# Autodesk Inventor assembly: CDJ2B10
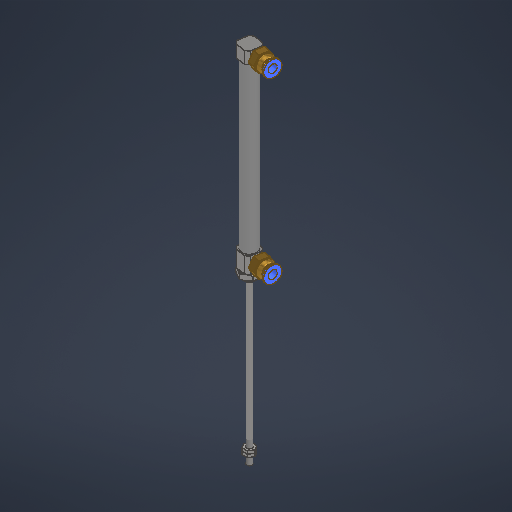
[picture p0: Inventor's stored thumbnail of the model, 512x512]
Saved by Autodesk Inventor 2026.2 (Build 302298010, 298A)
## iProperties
Created: 2026-05
Part Number: CDJ2B10
Document SubType Name: Assembly
Designer: work
Author: work
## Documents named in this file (6)
- C:\Users\work\Desktop\ARD_v1\ARD_hardware\Pneumatic fitting\CDJ2B10_100\CDJ2B10.iam
- C:\Users\work\Desktop\ARD_v1\ARD_hardware\Pneumatic fitting\CDJ2B10_100\Rod.ipt
- C:\Users\work\Desktop\ARD_v1\ARD_hardware\Pneumatic fitting\CDJ2B10_100\CDJ2B10_Body.ipt
- C:\Users\work\Desktop\ARD_v1\ARD_hardware\Pneumatic fitting\PC6-M5.ipt
- C:\Users\work\Desktop\ARD_v1\ARD_hardware\Pneumatic fitting\CDJ2B10_100\ANSI B18.2.4.5M - M8 x 1.25.ipt
- C:\Users\work\Desktop\ARD_v1\ARD_hardware\Pneumatic fitting\CDJ2B10_100\AS 1474 - M4(1).ipt
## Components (7 placed, 5 different names)
1. Rod:1 — 플러쉬:1, 플러쉬:2
2. CDJ2B10_Body:1 — 플러쉬:1
3. PC6-M5:1
4. PC6-M5:2
5. ANSI B18.2.4.5M - M8 x 1.25:1
6. AS 1474 - M4(1):1
7. AS 1474 - M4(1):2 — 플러쉬:2
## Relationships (2: Flush 2)
- 플러쉬:1 [Flush]: Rod:1 ↔ CDJ2B10_Body:1
- 플러쉬:2 [Flush]: Rod:1 ↔ AS 1474 - M4(1):2
